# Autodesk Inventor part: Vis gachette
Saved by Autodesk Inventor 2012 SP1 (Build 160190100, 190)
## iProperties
Created: 2014-12
Part Number: Vis gachette
Material: Default
Document SubType Name: Modeling
Designer: Bruno
Density: 1 g/cm^3
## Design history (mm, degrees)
node "Vis gachette1"
node "Vis gachette"
node "Base1"
